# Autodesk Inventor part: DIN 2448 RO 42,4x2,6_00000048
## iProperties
Created: 2006-03
Part Number: DIN 2448 RO 42,4x2,6_00000048
Material: Default
Document SubType Name: Modeling
Designer: Carlo
Stock Number: DIN 2448 RO 42,4x2,6
Mass: 507.137 g
Surface Area: 3914.3 cm^2
Volume: 507.137 cm^3
Density: 1 g/cm^3
G_L: 1590.000 mm
G_W: 42.400 mm
G_H: 42.400 mm
AFG_Item: 42.4 x 2.6
CSToolsMass: 1.0
CSToolsVolume: 507137.0
CSToolsArea: 3914.0
Author: Carlo
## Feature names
1. AFG_Detailed_DIN 2448 RO 42,4x2,6_00000048 [Extrusion]
2. AFG_Simplified_DIN 2448 RO 42,4x2,6_00000048 [Extrusion]
3. AFG_StartExtrusion_1 [Extrusion]
4. AFG_StartExtrusion_2 [Extrusion]
5. AFG_EndExtrusion_1 [Extrusion]
6. AFG_EndExtrusion_2 [Extrusion]
